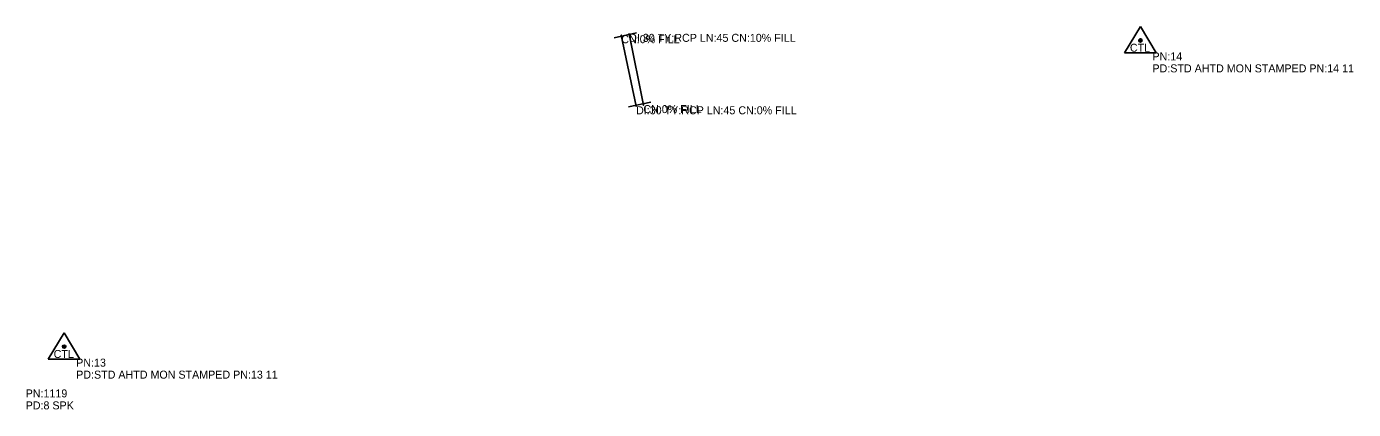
# Model space of a CAD drawing. Extents: x 1451369 to 1458940, y 1868647 to 1875095.
# Drawn here: x 1455590 to 1456419, y 1873648 to 1873887 of the extents above; entities that cross this region are included whole.
import ezdxf

# ---------------------------------------------------------------- set-up
doc = ezdxf.new("R2010")
doc.units = 0
for name, color, linetype in [('E_Tract Number', 7, 'Continuous'), ('R_No Plot', 7, 'Continuous'), ('S_CROSS_DRAIN', 7, 'Continuous'), ('S_CROSS_DRAIN_ANNOT', 7, 'Continuous'), ('S_HEADWALL', 7, 'Continuous'), ('S_PRIMARY_CTL_ANNOT', 7, 'Continuous'), ('S_SECONDARY_CTL_ANNOT', 7, 'Continuous')]:
    doc.layers.add(name, color=color, linetype=linetype)

msp = doc.modelspace()

# ---------------------------------------------------------------- linework, layer by layer
at = {"layer": 'E_Tract Number'}
for points in [[(1455966.38, 1873882.65), (1455966.38, 1873882.7), (1455966.38, 1873882.65), (1455966.33, 1873882.65), (1455966.38, 1873882.65), (1455966.38, 1873882.6), (1455966.38, 1873882.65), (1455966.43, 1873882.65)], [(1455961.47, 1873881.77), (1455961.47, 1873881.82), (1455961.47, 1873881.77), (1455961.42, 1873881.77), (1455961.47, 1873881.77), (1455961.47, 1873881.72), (1455961.47, 1873881.77), (1455961.52, 1873881.77)], [(1455970.7, 1873837.31), (1455970.7, 1873837.36), (1455970.7, 1873837.31), (1455970.65, 1873837.31), (1455970.7, 1873837.31), (1455970.7, 1873837.26), (1455970.7, 1873837.31), (1455970.75, 1873837.31)], [(1455975.26, 1873838.05), (1455975.26, 1873838.1), (1455975.26, 1873838.05), (1455975.21, 1873838.05), (1455975.26, 1873838.05), (1455975.26, 1873838), (1455975.26, 1873838.05), (1455975.31, 1873838.05)]]:
    msp.add_lwpolyline(points, dxfattribs=at)
at = {"layer": 'R_No Plot'}
for p, q in [((1456285.93, 1873887.24), (1456275.9, 1873870.72)), ((1456285.93, 1873887.24), (1456295.76, 1873870.72)), ((1456275.9, 1873870.72), (1456295.76, 1873870.72)), ((1455613.3, 1873695.6), (1455603.27, 1873679.08)), ((1455613.3, 1873695.6), (1455623.13, 1873679.08)), ((1455603.27, 1873679.08), (1455623.13, 1873679.08))]:
    msp.add_line(p, q, dxfattribs=at)
for centre, radius in [((1456285.93, 1873878.54), 1.04), ((1456285.93, 1873878.54), 0.609), ((1456285.93, 1873878.54), 0.344), ((1455613.3, 1873686.9), 1.04), ((1455613.3, 1873686.9), 0.609), ((1455613.3, 1873686.9), 0.344)]:
    msp.add_circle(centre, radius, dxfattribs=at)
at = {"layer": 'S_CROSS_DRAIN'}
for p, q in [((1455966.38, 1873882.65), (1455975.26, 1873838.05)), ((1455970.7, 1873837.31), (1455961.47, 1873881.77))]:
    msp.add_line(p, q, dxfattribs=at)
at = {"layer": 'S_HEADWALL'}
for points in [[(1455957.02, 1873880.24), (1455971.05, 1873883.2)], [(1455979.93, 1873839.85), (1455966.07, 1873836.89)]]:
    msp.add_lwpolyline(points, dxfattribs=at)

# ---------------------------------------------------------------- texts
at = {"layer": 'R_No Plot'}
for p in [(1456279.35, 1873871.46), (1455606.72, 1873679.82)]:
    msp.add_text('CTL', height=5, rotation=360, dxfattribs=at).set_placement(p)
at = {"layer": 'S_CROSS_DRAIN_ANNOT'}
for s, p in [('DI:30 TY:RCP LN:45 CN:10% FILL', (1455966.38, 1873877.65)), ('CN:0% FILL', (1455961.47, 1873876.77)), ('DI:30 TY:RCP LN:45 CN:0% FILL', (1455970.7, 1873832.31)), ('CN:0% FILL', (1455975.26, 1873833.05))]:
    msp.add_text(s, height=5, dxfattribs=at).set_placement(p)
at = {"layer": 'S_PRIMARY_CTL_ANNOT'}
for s, p in [('PN:14', (1456293.43, 1873866.04)), ('PD:STD AHTD MON STAMPED PN:14 11', (1456293.43, 1873858.54)), ('PN:13', (1455620.8, 1873674.4)), ('PD:STD AHTD MON STAMPED PN:13 11', (1455620.8, 1873666.9))]:
    msp.add_text(s, height=5, dxfattribs=at).set_placement(p)
at = {"layer": 'S_SECONDARY_CTL_ANNOT'}
for s, p in [('PN:1119', (1455589.23, 1873655.15)), ('PD:8 SPK', (1455589.23, 1873647.65))]:
    msp.add_text(s, height=5, dxfattribs=at).set_placement(p)

doc.saveas('drawing.dxf')
